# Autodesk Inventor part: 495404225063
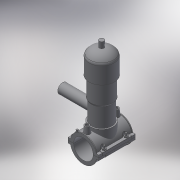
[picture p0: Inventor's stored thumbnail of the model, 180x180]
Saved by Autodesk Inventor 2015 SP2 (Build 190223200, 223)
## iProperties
Created: 2017-07
Part Number: 495404225063
Material: Generic
Description: PLASSON TAPPING VALVE 225-63
Document SubType Name: Modeling
Designer: KIM
Density: 1 g/cm^3
Appearance: Default
Author: KIM
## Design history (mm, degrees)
derived "495404-4954S4.ipt"
feature "Solid1::495404-4954S4.ipt"
feature "Solid2::495404-4954S4.ipt"
tag "TaggingFeature1"
body "Solid1"
body "Solid2"
other parameters: "d0" = 225, "d2" = 295.1, "d3" = 56.25, "d4" = 176, "d5" = 0, "d6" = 0.1, "d8" = 0, "d19" = 6, "d20" = 6, "d21" = 105.6, "d23" = 0, "d24" = 52.8, "d26" = 0, "d27" = 3, "d28" = 3, "d29" = 3, "d30" = 75, "d31" = 6, "d32" = 0, "d33" = 0, "d34" = 0.6, "d40" = 136.89, "d47" = 182.625, "d70" = 15, "d72" = 0, "d73" = 6, "d75" = 5, "d76" = 0, "d77" = 11.25, "d78" = 142.5, "d79" = 15, "d80" = 70.4, "d82" = 5 deg, "d84" = 4, "d85" = 14, "d86" = 0, "d87" = 3, "d88" = 0, "d89" = 1, "d90" = 1, "d91" = 140.8, "d92" = 0, "d93" = 0.5, "d94" = 118.42105, "d96" = 271.1475, "d97" = 3.52, "d98" = 0, "d120" = 140 deg, "d121" = 24.228, "d122" = 20 deg, "d123" = 526.5, "d124" = 157.95, "d126" = 0, "d143" = 231.75, "d145" = 29.42308, "d149" = 3.375, "d150" = 32.36538, "d153" = 176, "d154" = 0, "d156" = 131.625, "d157" = 160 deg, "d159" = 7.65, "d161" = 3.375, "d162" = 105.6, "d163" = 0, "d164" = 112.5, "d167" = 22.5, "d168" = 128.41463, "d170" = 3.375, "d172" = 0, "d173" = 1, "d175" = 112.5, "d176" = 20 deg, "d177" = 15.75, "d178" = 38.25, "d180" = 0, "d183" = 15.3, "d184" = 12.6, "d185" = 57.2, "d186" = 57.2, "d187" = 131.625, "d188" = 11.475, "d189" = 15.75, "d190" = 0, "d191" = 197.4375, "d193" = 7.65, "d194" = 4.4, "d195" = 90 deg, "d197" = 0, "d199" = 0, "d205" = 14.64, "d206" = 81.33333, "d207" = 244, "d208" = 224.48, "d209" = 207.4, "d210" = 200.08, "d211" = 146.4, "d212" = 85.4, "d213" = 65.88, "d214" = 73.2, "d216" = 21.96, "d217" = 70.76, "d218" = 80.52, "d220" = 225, "d222" = 0, "d223" = 263.25, "d224" = 186, "d225" = 51, "d226" = 63, "d229" = 186, "d230" = 0, "d_" = 225, "B_" = 227, "H_" = 186, "L_" = 176, "d_t" = 6, "d_1" = 63, "H_1" = 51, "H_2" = 244, "d148" = 3.375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
